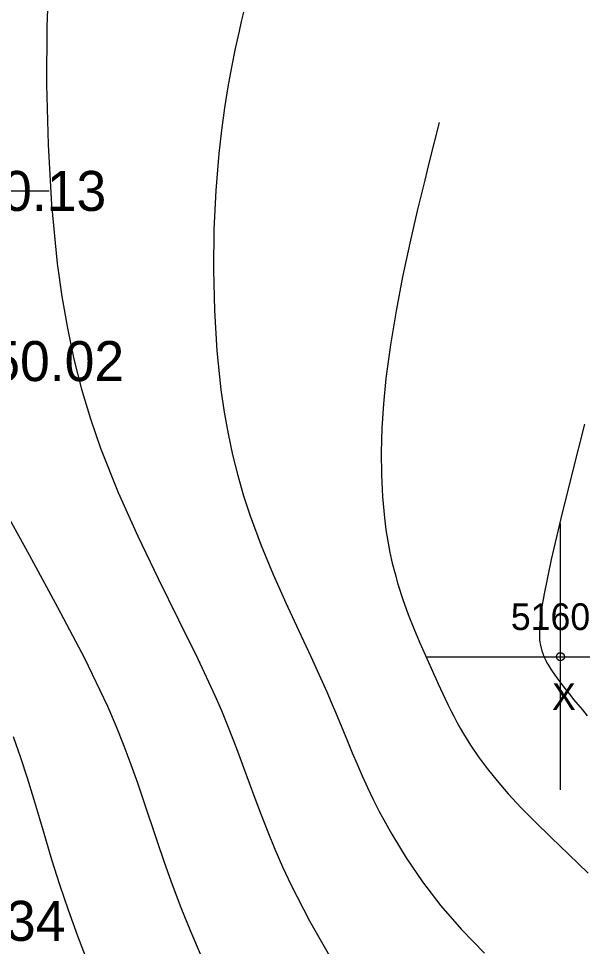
# Model space of a CAD drawing. Extents: x 1378535 to 1380697, y 997729 to 1000024.
# Drawn here: x 1379921.45 to 1379942.59, y 998852.85 to 998887.65 of the extents above; entities that cross this region are included whole.
import ezdxf

# ---------------------------------------------------------------- set-up
doc = ezdxf.new("R2010")
doc.units = 0
for name, color, linetype in [('RD_DTM_Major1', 7, 'Continuous'), ('RD_DTM_Minor1', 7, 'Continuous'), ('RD_EX_Misc', 7, 'Continuous'), ('RD_EX_Misc_txCode', 7, 'Continuous'), ('RD_EX_TX_H2O_ELEV', 7, 'Continuous'), ('RD_EX_TX_Misc_ELEV', 7, 'Continuous'), ('RD_SMD_Locator', 7, 'Continuous')]:
    doc.layers.add(name, color=color, linetype=linetype)

msp = doc.modelspace()

# ---------------------------------------------------------------- linework, layer by layer
at = {"layer": 'RD_DTM_Major1'}
msp.add_lwpolyline([(1379920.778, 998869.467), (1379921.844, 998867.532), (1379922.914, 998865.578), (1379923.917, 998863.664), (1379924.784, 998861.854), (1379925.108, 998861.102), (1379925.397, 998860.377), (1379925.66, 998859.673), (1379925.903, 998858.985), (1379926.133, 998858.308), (1379926.626, 998856.824), (1379926.906, 998856.005), (1379927.204, 998855.169), (1379927.529, 998854.309), (1379927.89, 998853.418), (1379928.295, 998852.485)], dxfattribs=at)
at = {"layer": 'RD_DTM_Minor1'}
for points in [[(1379922.582, 998889.326), (1379922.513, 998887.339), (1379922.5, 998885.178), (1379922.553, 998882.925), (1379922.682, 998880.66), (1379922.897, 998878.465), (1379923.07, 998877.227), (1379923.278, 998876.034), (1379923.526, 998874.876), (1379923.814, 998873.746), (1379924.146, 998872.635), (1379924.525, 998871.534), (1379925.184, 998869.876), (1379925.917, 998868.239), (1379926.684, 998866.642), (1379927.447, 998865.102), (1379928.167, 998863.636), (1379928.806, 998862.263), (1379929.053, 998861.692), (1379929.28, 998861.14), (1379929.492, 998860.601), (1379929.693, 998860.073), (1379929.886, 998859.553), (1379930.306, 998858.412), (1379930.542, 998857.784), (1379930.791, 998857.148), (1379931.058, 998856.498), (1379931.349, 998855.831), (1379931.669, 998855.142), (1379932.351, 998853.805), (1379933.154, 998852.409)], [(1379929.882, 998887.888), (1379929.799, 998887.542), (1379929.716, 998887.184), (1379929.571, 998886.528), (1379929.429, 998885.83), (1379929.293, 998885.089), (1379929.167, 998884.303), (1379929.053, 998883.471), (1379928.954, 998882.592), (1379928.842, 998881.203), (1379928.774, 998879.736), (1379928.756, 998878.224), (1379928.791, 998876.696), (1379928.883, 998875.184), (1379929.037, 998873.719), (1379929.159, 998872.884), (1379929.305, 998872.074), (1379929.474, 998871.284), (1379929.667, 998870.511), (1379929.885, 998869.752), (1379930.128, 998869.004), (1379930.541, 998867.887), (1379930.993, 998866.794), (1379931.467, 998865.731), (1379931.944, 998864.705), (1379932.404, 998863.722), (1379932.831, 998862.789), (1379933.004, 998862.397), (1379933.168, 998862.014), (1379933.325, 998861.638), (1379933.478, 998861.27), (1379933.627, 998860.906), (1379933.775, 998860.545), (1379933.955, 998860.111), (1379934.138, 998859.678), (1379934.327, 998859.244), (1379934.527, 998858.805), (1379934.739, 998858.362), (1379934.967, 998857.91), (1379935.438, 998857.052), (1379935.978, 998856.17), (1379936.591, 998855.274), (1379937.281, 998854.373), (1379938.053, 998853.477), (1379938.911, 998852.596)], [(1379937.218, 998883.751), (1379936.857, 998882.333), (1379936.766, 998881.967), (1379936.673, 998881.594), (1379936.393, 998880.437), (1379936.113, 998879.221), (1379935.845, 998877.965), (1379935.6, 998876.688), (1379935.388, 998875.41), (1379935.221, 998874.15), (1379935.129, 998873.204), (1379935.069, 998872.284), (1379935.043, 998871.393), (1379935.049, 998870.533), (1379935.088, 998869.709), (1379935.161, 998868.924), (1379935.219, 998868.478), (1379935.289, 998868.046), (1379935.369, 998867.626), (1379935.46, 998867.217), (1379935.561, 998866.819), (1379935.671, 998866.43), (1379935.856, 998865.857), (1379936.056, 998865.303), (1379936.267, 998864.768), (1379936.483, 998864.254), (1379936.7, 998863.761), (1379936.912, 998863.29), (1379937.002, 998863.09), (1379937.091, 998862.894), (1379937.178, 998862.701), (1379937.265, 998862.511), (1379937.352, 998862.324), (1379937.439, 998862.139), (1379937.545, 998861.918), (1379937.653, 998861.698), (1379937.765, 998861.479), (1379937.881, 998861.259), (1379938.003, 998861.039), (1379938.132, 998860.817), (1379938.391, 998860.399), (1379938.683, 998859.968), (1379939.012, 998859.522), (1379939.385, 998859.056), (1379939.807, 998858.569), (1379940.283, 998858.057), (1379940.815, 998857.517), (1379941.409, 998856.937), (1379942.07, 998856.302), (1379942.8, 998855.601)], [(1379942.669, 998872.44), (1379942.2, 998870.61), (1379941.776, 998868.893), (1379941.42, 998867.357), (1379941.154, 998866.073), (1379941.116, 998865.863), (1379941.081, 998865.665), (1379941.052, 998865.477), (1379941.026, 998865.299), (1379941.005, 998865.131), (1379940.99, 998864.972), (1379940.977, 998864.796), (1379940.974, 998864.712), (1379940.972, 998864.63), (1379940.973, 998864.551), (1379940.975, 998864.474), (1379940.983, 998864.361), (1379940.995, 998864.251), (1379941.013, 998864.145), (1379941.037, 998864.04), (1379941.066, 998863.936), (1379941.101, 998863.832), (1379941.119, 998863.786), (1379941.138, 998863.739), (1379941.158, 998863.693), (1379941.179, 998863.646), (1379941.202, 998863.598), (1379941.227, 998863.55), (1379941.258, 998863.491), (1379941.291, 998863.431), (1379941.327, 998863.37), (1379941.365, 998863.307), (1379941.406, 998863.243), (1379941.449, 998863.177), (1379941.535, 998863.05), (1379941.63, 998862.916), (1379941.735, 998862.774), (1379941.85, 998862.624), (1379941.975, 998862.464), (1379942.111, 998862.293), (1379942.258, 998862.113), (1379942.416, 998861.921), (1379942.585, 998861.717), (1379942.767, 998861.501)], [(1379921.242, 998860.725), (1379921.521, 998859.938), (1379921.774, 998859.165), (1379922.009, 998858.401), (1379922.235, 998857.64), (1379922.459, 998856.879), (1379922.688, 998856.113), (1379922.984, 998855.176), (1379923.305, 998854.219), (1379923.659, 998853.24), (1379924.051, 998852.233)]]:
    msp.add_lwpolyline(points, dxfattribs=at)
at = {"layer": 'RD_EX_Misc'}
for p, q in [((1379912.601, 998881.186), (1379922.601, 998881.186)), ((1379941.761, 998858.716), (1379941.761, 998868.716)), ((1379936.761, 998863.716), (1379946.761, 998863.716))]:
    msp.add_line(p, q, dxfattribs=at)
at = {"layer": 'RD_SMD_Locator'}
msp.add_circle((1379941.761, 998863.716), 0.15, dxfattribs=at)

# ---------------------------------------------------------------- texts
at = {"layer": 'RD_EX_Misc_txCode'}
for s, p in [('51608', (1379939.903, 998864.716)), ('X', (1379941.446, 998861.716))]:
    msp.add_text(s, height=1, dxfattribs=at).set_placement(p)
at = {"layer": 'RD_EX_TX_H2O_ELEV'}
msp.add_text('747.34', height=1.5, dxfattribs=at).set_placement((1379917.07, 998853.057))
at = {"layer": 'RD_EX_TX_Misc_ELEV'}
for s, p in [('750.13', (1379918.601, 998880.436)), ('750.02', (1379919.272, 998874.052))]:
    msp.add_text(s, height=1.5, dxfattribs=at).set_placement(p)

doc.saveas('drawing.dxf')
